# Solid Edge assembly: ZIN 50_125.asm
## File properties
Title: Zylinder
Author: bmolnar
Template: iso metric assembly.asm
Last saved by: bmolnar
Revision: 28
Application: Solid Edge
Username: bmolnar
Dokumentum tartalom típus: 1
Document Number: ZIN 50/125
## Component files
Profilrohr.par
Kolbenstange.par
Kit_2.par
Kit_1.par
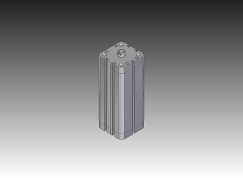
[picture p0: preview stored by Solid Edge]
